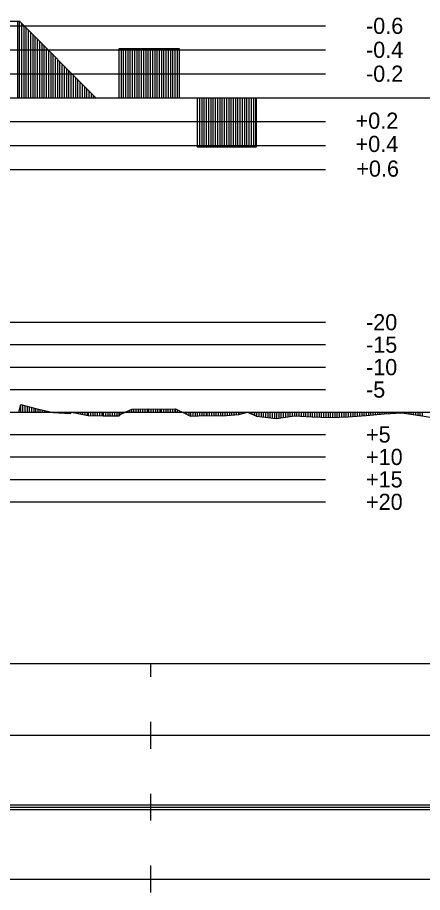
# Model space of a CAD drawing. Extents: x 2 to 10148, y 0 to 380.
# Drawn here: x 2583.7 to 2628.8, y 188.5 to 285.9 of the extents above; entities that cross this region are included whole.
import ezdxf

# ---------------------------------------------------------------- set-up
doc = ezdxf.new("R2010")
doc.units = 0
for name, color, linetype in [('POSUN_CARA', 7, 'Continuous'), ('POSUN_RASTR', 7, 'Continuous'), ('POSUN_TEXT', 7, 'Continuous'), ('RYCHL_RASTR', 7, 'Continuous'), ('ZRYCHL_CARA', 7, 'Continuous'), ('ZRYCHL_RASTR', 7, 'Continuous'), ('ZRYCHL_TEXT', 7, 'Continuous')]:
    doc.layers.add(name, color=color, linetype=linetype)

msp = doc.modelspace()

# ---------------------------------------------------------------- linework, layer by layer
at = {"layer": 'POSUN_CARA'}
for p, q in [((2583.828, 242.001), (2584.047, 242.828)), ((2584.047, 242.828), (2585.728, 242.389)), ((2584.047, 242), (2584.047, 242.828)), ((2584.297, 242), (2584.297, 242.762)), ((2584.547, 242), (2584.547, 242.697)), ((2584.797, 242), (2584.797, 242.632)), ((2583.828, 242), (2583.828, 242.001)), ((2585.047, 242), (2585.047, 242.567)), ((2585.297, 242), (2585.297, 242.501)), ((2585.547, 242), (2585.547, 242.436)), ((2585.728, 242.389), (2587.655, 241.939)), ((2585.728, 242), (2585.728, 242.389)), ((2585.978, 242), (2585.978, 242.33)), ((2586.228, 242), (2586.228, 242.272)), ((2586.478, 242), (2586.478, 242.214)), ((2586.728, 242), (2586.728, 242.155)), ((2586.978, 242), (2586.978, 242.097)), ((2587.228, 242), (2587.228, 242.039)), ((2587.478, 242), (2587.478, 241.98)), ((2587.655, 242), (2587.655, 241.939)), ((2587.655, 241.939), (2589.578, 241.82)), ((2587.905, 242), (2587.905, 241.923)), ((2588.155, 242), (2588.155, 241.908)), ((2588.405, 242), (2588.405, 241.892)), ((2588.655, 242), (2588.655, 241.877)), ((2588.905, 242), (2588.905, 241.861)), ((2589.155, 242), (2589.155, 241.846)), ((2589.405, 242), (2589.405, 241.831)), ((2589.578, 242), (2589.578, 241.82)), ((2589.578, 241.82), (2589.696, 241.998)), ((2589.696, 242), (2589.696, 241.998)), ((2589.696, 241.998), (2591.567, 241.603)), ((2589.946, 242), (2589.946, 241.946)), ((2590.196, 242), (2590.196, 241.893)), ((2590.446, 242), (2590.446, 241.84)), ((2590.696, 242), (2590.696, 241.787)), ((2590.946, 242), (2590.946, 241.734)), ((2591.196, 242), (2591.196, 241.681)), ((2591.446, 242), (2591.446, 241.629)), ((2591.567, 242), (2591.567, 241.603)), ((2591.817, 242), (2591.817, 241.596)), ((2592.067, 242), (2592.067, 241.59)), ((2592.317, 242), (2592.317, 241.584)), ((2592.567, 242), (2592.567, 241.577)), ((2592.817, 242), (2592.817, 241.571)), ((2593.067, 242), (2593.067, 241.565)), ((2593.239, 242), (2593.239, 241.56)), ((2593.489, 242), (2593.489, 241.563)), ((2593.739, 242), (2593.739, 241.566)), ((2593.989, 242), (2593.989, 241.568)), ((2594.239, 242), (2594.239, 241.571)), ((2594.489, 242), (2594.489, 241.573)), ((2594.739, 242), (2594.739, 241.576)), ((2594.989, 242), (2594.989, 241.578)), ((2595.006, 242), (2595.006, 241.579)), ((2595.006, 241.579), (2595.202, 241.752)), ((2595.202, 241.752), (2596.406, 242.302)), ((2595.202, 242), (2595.202, 241.752)), ((2595.452, 242), (2595.452, 241.866)), ((2595.702, 242), (2595.702, 241.98)), ((2595.952, 242), (2595.952, 242.095)), ((2596.202, 242), (2596.202, 242.209)), ((2596.406, 242.302), (2598.33, 242.37)), ((2596.406, 242), (2596.406, 242.302)), ((2596.656, 242), (2596.656, 242.311)), ((2596.906, 242), (2596.906, 242.32)), ((2597.156, 242), (2597.156, 242.329)), ((2597.406, 242), (2597.406, 242.337)), ((2597.656, 242), (2597.656, 242.346)), ((2597.906, 242), (2597.906, 242.355)), ((2598.156, 242), (2598.156, 242.364)), ((2598.33, 242.37), (2599.732, 242.329)), ((2598.33, 242), (2598.33, 242.37)), ((2598.58, 242), (2598.58, 242.362)), ((2598.83, 242), (2598.83, 242.355)), ((2599.08, 242), (2599.08, 242.348)), ((2599.33, 242), (2599.33, 242.341)), ((2599.58, 242), (2599.58, 242.333)), ((2599.732, 242.329), (2601.277, 242.348)), ((2599.732, 242), (2599.732, 242.329)), ((2599.982, 242), (2599.982, 242.332)), ((2600.232, 242), (2600.232, 242.335)), ((2600.482, 242), (2600.482, 242.338)), ((2600.732, 242), (2600.732, 242.341)), ((2600.982, 242), (2600.982, 242.345)), ((2601.232, 242), (2601.232, 242.348)), ((2601.277, 242.348), (2602.96, 241.532)), ((2601.277, 242), (2601.277, 242.348)), ((2601.527, 242), (2601.527, 242.227)), ((2601.777, 242), (2601.777, 242.106)), ((2602.027, 242), (2602.027, 241.985)), ((2602.277, 242), (2602.277, 241.864)), ((2602.527, 242), (2602.527, 241.742)), ((2602.777, 242), (2602.777, 241.621)), ((2602.96, 242), (2602.96, 241.532)), ((2603.21, 242), (2603.21, 241.541)), ((2603.46, 242), (2603.46, 241.549)), ((2603.71, 242), (2603.71, 241.558)), ((2603.96, 242), (2603.96, 241.566)), ((2604.21, 242), (2604.21, 241.575)), ((2604.46, 242), (2604.46, 241.583)), ((2604.71, 242), (2604.71, 241.591)), ((2604.793, 242), (2604.793, 241.594)), ((2605.043, 242), (2605.043, 241.591)), ((2605.293, 242), (2605.293, 241.589)), ((2605.543, 242), (2605.543, 241.586)), ((2605.793, 242), (2605.793, 241.583)), ((2606.043, 242), (2606.043, 241.581)), ((2606.293, 242), (2606.293, 241.578)), ((2606.538, 242), (2606.538, 241.575)), ((2606.538, 241.575), (2608.328, 241.708)), ((2606.788, 242), (2606.788, 241.594)), ((2607.038, 242), (2607.038, 241.612)), ((2607.288, 242), (2607.288, 241.631)), ((2607.538, 242), (2607.538, 241.649)), ((2607.788, 242), (2607.788, 241.668)), ((2608.038, 242), (2608.038, 241.686)), ((2608.288, 242), (2608.288, 241.705)), ((2608.328, 242), (2608.328, 241.708)), ((2608.328, 241.708), (2609.287, 241.998)), ((2608.578, 242), (2608.578, 241.783)), ((2608.828, 242), (2608.828, 241.859)), ((2609.078, 242), (2609.078, 241.935)), ((2609.287, 242), (2609.287, 241.998)), ((2609.287, 241.998), (2610.309, 241.522)), ((2609.537, 242), (2609.537, 241.882)), ((2609.787, 242), (2609.787, 241.765)), ((2610.037, 242), (2610.037, 241.649)), ((2610.287, 242), (2610.287, 241.532)), ((2610.309, 242), (2610.309, 241.522)), ((2610.559, 242), (2610.559, 241.496)), ((2610.809, 242), (2610.809, 241.471)), ((2611.059, 242), (2611.059, 241.445)), ((2611.309, 242), (2611.309, 241.419)), ((2611.559, 242), (2611.559, 241.394)), ((2611.809, 242), (2611.809, 241.368)), ((2612.059, 242), (2612.059, 241.342)), ((2612.309, 242), (2612.309, 241.317)), ((2612.527, 242), (2612.527, 241.295)), ((2612.777, 242), (2612.777, 241.328)), ((2613.027, 242), (2613.027, 241.361)), ((2613.277, 242), (2613.277, 241.394)), ((2613.527, 242), (2613.527, 241.427)), ((2613.777, 242), (2613.777, 241.46)), ((2614.027, 242), (2614.027, 241.493)), ((2614.277, 242), (2614.277, 241.526)), ((2614.525, 242), (2614.525, 241.559)), ((2614.775, 242), (2614.775, 241.547)), ((2615.025, 242), (2615.025, 241.534)), ((2615.275, 242), (2615.275, 241.522)), ((2615.525, 242), (2615.525, 241.509)), ((2615.775, 242), (2615.775, 241.497)), ((2616.025, 242), (2616.025, 241.485)), ((2616.275, 242), (2616.275, 241.472)), ((2616.521, 242), (2616.521, 241.46)), ((2616.771, 242), (2616.771, 241.453)), ((2617.021, 242), (2617.021, 241.446)), ((2617.271, 242), (2617.271, 241.439)), ((2617.521, 242), (2617.521, 241.432)), ((2617.771, 242), (2617.771, 241.425)), ((2618.021, 242), (2618.021, 241.419)), ((2618.271, 242), (2618.271, 241.412)), ((2618.52, 242), (2618.52, 241.405)), ((2618.77, 242), (2618.77, 241.41)), ((2619.02, 242), (2619.02, 241.416)), ((2619.27, 242), (2619.27, 241.421)), ((2619.52, 242), (2619.52, 241.427)), ((2619.77, 242), (2619.77, 241.432)), ((2620.02, 242), (2620.02, 241.437)), ((2620.27, 242), (2620.27, 241.443)), ((2620.52, 242), (2620.52, 241.448)), ((2620.52, 241.448), (2622.515, 241.63)), ((2620.77, 242), (2620.77, 241.471)), ((2621.02, 242), (2621.02, 241.494)), ((2621.27, 242), (2621.27, 241.517)), ((2621.52, 242), (2621.52, 241.54)), ((2621.77, 242), (2621.77, 241.562)), ((2622.02, 242), (2622.02, 241.585)), ((2622.27, 242), (2622.27, 241.608)), ((2622.515, 242), (2622.515, 241.63)), ((2622.515, 241.63), (2624.513, 241.814)), ((2622.765, 242), (2622.765, 241.653)), ((2623.015, 242), (2623.015, 241.676)), ((2623.265, 242), (2623.265, 241.699)), ((2623.515, 242), (2623.515, 241.722)), ((2623.765, 242), (2623.765, 241.745)), ((2624.015, 242), (2624.015, 241.768)), ((2624.265, 242), (2624.265, 241.791)), ((2624.513, 242), (2624.513, 241.814)), ((2624.513, 241.814), (2626.506, 241.918)), ((2624.763, 242), (2624.763, 241.827)), ((2625.013, 242), (2625.013, 241.84)), ((2625.263, 242), (2625.263, 241.853)), ((2625.513, 242), (2625.513, 241.866)), ((2625.763, 242), (2625.763, 241.879)), ((2626.013, 242), (2626.013, 241.892)), ((2626.263, 242), (2626.263, 241.905)), ((2626.506, 242), (2626.506, 241.918)), ((2626.506, 241.918), (2628.5, 241.611)), ((2626.756, 242), (2626.756, 241.88)), ((2627.006, 242), (2627.006, 241.841)), ((2627.256, 242), (2627.256, 241.803)), ((2627.506, 242), (2627.506, 241.764)), ((2627.756, 242), (2627.756, 241.726)), ((2628.006, 242), (2628.006, 241.687)), ((2628.256, 242), (2628.256, 241.649)), ((2628.5, 242), (2628.5, 241.611)), ((2628.75, 242), (2628.75, 241.568)), ((2591.567, 241.603), (2593.239, 241.56)), ((2593.239, 241.56), (2595.006, 241.579)), ((2602.96, 241.532), (2604.793, 241.594)), ((2604.793, 241.594), (2606.538, 241.575)), ((2610.309, 241.522), (2612.527, 241.295)), ((2612.527, 241.295), (2614.525, 241.559)), ((2614.525, 241.559), (2616.521, 241.46)), ((2616.521, 241.46), (2618.52, 241.405)), ((2618.52, 241.405), (2620.52, 241.448)), ((2628.5, 241.611), (2629.901, 241.372))]:
    msp.add_line(p, q, dxfattribs=at)
at = {"layer": 'POSUN_RASTR'}
for p, q in [((2422, 252), (2618, 252)), ((2422, 249.5), (2618, 249.5)), ((2422, 247), (2618, 247)), ((2422, 244.5), (2618, 244.5)), ((2328.7, 242), (3155.543, 242)), ((2422, 239.5), (2618, 239.5)), ((2422, 237), (2618, 237)), ((2422, 234.5), (2618, 234.5)), ((2422, 232), (2618, 232))]:
    msp.add_line(p, q, dxfattribs=at)
at = {"layer": 'RYCHL_RASTR'}
for p, q in [((2328.7, 214), (3155.543, 214)), ((2598.554, 212.5), (2598.554, 214)), ((2598.554, 204.5), (2598.554, 207.5)), ((2328.7, 206), (3155.543, 206)), ((2598.554, 196.5), (2598.554, 199.5)), ((2328.7, 198.25), (3155.543, 198.25)), ((2328.7, 198), (3155.543, 198)), ((2328.7, 197.75), (3155.543, 197.75)), ((2598.554, 188.5), (2598.554, 191.5)), ((2328.7, 190), (3155.543, 190))]:
    msp.add_line(p, q, dxfattribs=at)
at = {"layer": 'ZRYCHL_CARA'}
for p, q in [((2580.72, 285.509), (2583.923, 285.509)), ((2583.72, 277), (2583.72, 285.509)), ((2583.923, 277), (2583.923, 285.509)), ((2583.923, 285.509), (2592.423, 277)), ((2584.173, 277), (2584.173, 285.259)), ((2584.423, 277), (2584.423, 285.009)), ((2584.673, 277), (2584.673, 284.758)), ((2584.923, 277), (2584.923, 284.508)), ((2585.173, 277), (2585.173, 284.258)), ((2585.423, 277), (2585.423, 284.008)), ((2585.673, 277), (2585.673, 283.757)), ((2585.923, 277), (2585.923, 283.507)), ((2586.173, 277), (2586.173, 283.257)), ((2586.423, 277), (2586.423, 283.007)), ((2586.673, 277), (2586.673, 282.756)), ((2586.923, 277), (2586.923, 282.506)), ((2587.173, 277), (2587.173, 282.256)), ((2587.423, 277), (2587.423, 282.005)), ((2587.673, 277), (2587.673, 281.755)), ((2595.005, 277), (2595.005, 282.47)), ((2595.005, 277), (2595.005, 282.47)), ((2595.005, 282.47), (2601.696, 282.47)), ((2595.255, 277), (2595.255, 282.47)), ((2595.505, 277), (2595.505, 282.47)), ((2595.755, 277), (2595.755, 282.47)), ((2596.005, 277), (2596.005, 282.47)), ((2596.255, 277), (2596.255, 282.47)), ((2596.505, 277), (2596.505, 282.47)), ((2596.755, 277), (2596.755, 282.47)), ((2597.005, 277), (2597.005, 282.47)), ((2597.255, 277), (2597.255, 282.47)), ((2597.505, 277), (2597.505, 282.47)), ((2597.755, 277), (2597.755, 282.47)), ((2598.005, 277), (2598.005, 282.47)), ((2598.255, 277), (2598.255, 282.47)), ((2598.505, 277), (2598.505, 282.47)), ((2598.755, 277), (2598.755, 282.47)), ((2599.005, 277), (2599.005, 282.47)), ((2599.255, 277), (2599.255, 282.47)), ((2599.505, 277), (2599.505, 282.47)), ((2599.755, 277), (2599.755, 282.47)), ((2600.005, 277), (2600.005, 282.47)), ((2600.255, 277), (2600.255, 282.47)), ((2600.505, 277), (2600.505, 282.47)), ((2600.755, 277), (2600.755, 282.47)), ((2601.005, 277), (2601.005, 282.47)), ((2601.255, 277), (2601.255, 282.47)), ((2601.505, 277), (2601.505, 282.47)), ((2601.696, 282.47), (2601.696, 277)), ((2587.923, 277), (2587.923, 281.505)), ((2588.173, 277), (2588.173, 281.255)), ((2588.423, 277), (2588.423, 281.004)), ((2588.673, 277), (2588.673, 280.754)), ((2588.923, 277), (2588.923, 280.504)), ((2589.173, 277), (2589.173, 280.254)), ((2589.423, 277), (2589.423, 280.003)), ((2589.673, 277), (2589.673, 279.753)), ((2589.923, 277), (2589.923, 279.503)), ((2590.173, 277), (2590.173, 279.252)), ((2590.423, 277), (2590.423, 279.002)), ((2590.673, 277), (2590.673, 278.752)), ((2590.923, 277), (2590.923, 278.502)), ((2591.173, 277), (2591.173, 278.251)), ((2591.423, 277), (2591.423, 278.001)), ((2591.673, 277), (2591.673, 277.751)), ((2328.7, 277), (3155.543, 277)), ((2591.923, 277), (2591.923, 277.501)), ((2592.173, 277), (2592.173, 277.25)), ((2603.708, 277), (2603.708, 271.53)), ((2603.708, 277), (2603.708, 271.53)), ((2603.958, 277), (2603.958, 271.53)), ((2604.208, 277), (2604.208, 271.53)), ((2604.458, 277), (2604.458, 271.53)), ((2604.708, 277), (2604.708, 271.53)), ((2604.958, 277), (2604.958, 271.53)), ((2605.208, 277), (2605.208, 271.53)), ((2605.458, 277), (2605.458, 271.53)), ((2605.708, 277), (2605.708, 271.53)), ((2605.958, 277), (2605.958, 271.53)), ((2606.208, 277), (2606.208, 271.53)), ((2606.458, 277), (2606.458, 271.53)), ((2606.708, 277), (2606.708, 271.53)), ((2606.958, 277), (2606.958, 271.53)), ((2607.208, 277), (2607.208, 271.53)), ((2607.458, 277), (2607.458, 271.53)), ((2607.708, 277), (2607.708, 271.53)), ((2607.958, 277), (2607.958, 271.53)), ((2608.208, 277), (2608.208, 271.53)), ((2608.458, 277), (2608.458, 271.53)), ((2608.708, 277), (2608.708, 271.53)), ((2608.958, 277), (2608.958, 271.53)), ((2609.208, 277), (2609.208, 271.53)), ((2609.458, 277), (2609.458, 271.53)), ((2609.708, 277), (2609.708, 271.53)), ((2609.958, 277), (2609.958, 271.53)), ((2610.208, 277), (2610.208, 271.53)), ((2610.312, 271.53), (2610.312, 277)), ((2603.708, 271.53), (2610.312, 271.53))]:
    msp.add_line(p, q, dxfattribs=at)
at = {"layer": 'ZRYCHL_RASTR'}
for p, q in [((2416.898, 285), (2618, 285)), ((2416.958, 282.333), (2618, 282.333)), ((2416.958, 279.667), (2618, 279.667)), ((2417.785, 274.333), (2618, 274.333)), ((2417.697, 271.667), (2618, 271.667)), ((2417.917, 269), (2618, 269))]:
    msp.add_line(p, q, dxfattribs=at)

# ---------------------------------------------------------------- texts
at = {"layer": 'POSUN_TEXT'}
for s, p in [('-20', (2622.5, 251.1)), ('-15', (2622.5, 248.6)), ('-10', (2622.5, 246.1)), ('-5', (2622.5, 243.6)), ('+5', (2622.5, 238.6)), ('+10', (2622.5, 236.1)), ('+15', (2622.5, 233.6)), ('+20', (2622.5, 231.1))]:
    msp.add_text(s, height=1.8, dxfattribs=at).set_placement(p)
at = {"layer": 'ZRYCHL_TEXT'}
for s, p in [('-0.6', (2622.5, 284.1)), ('-0.4', (2622.5, 281.433)), ('-0.2', (2622.5, 278.767)), ('+0.2', (2621.341, 273.539)), ('+0.4', (2621.341, 270.951)), ('+0.6', (2621.42, 268.205))]:
    msp.add_text(s, height=1.8, dxfattribs=at).set_placement(p)

doc.saveas('drawing.dxf')
